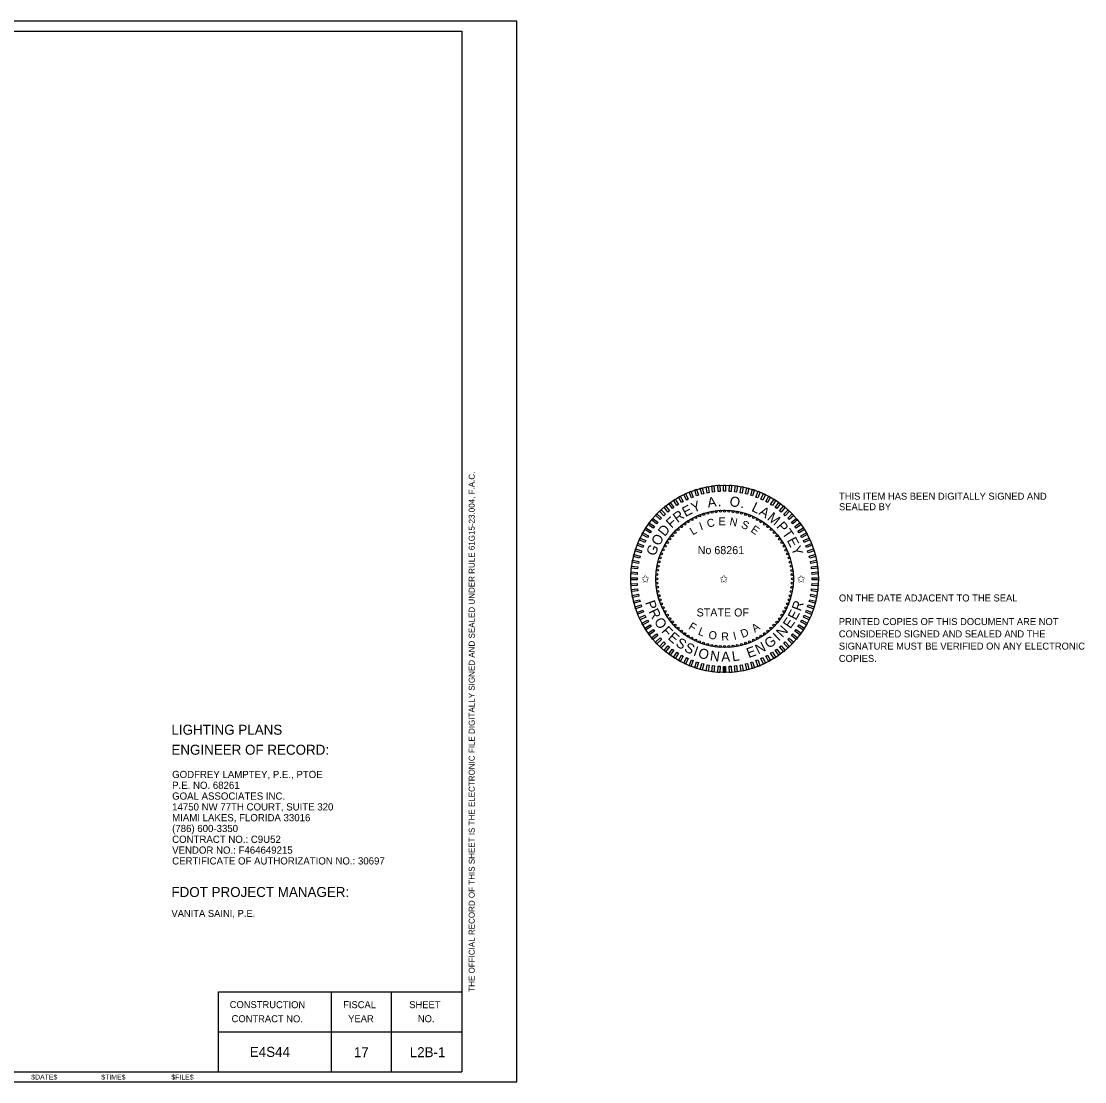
# Model space of a CAD drawing. Extents: x -820.2 to -798.1, y -2199.1 to -2188.5.
# Drawn here: x -808.68 to -798.05, y -2199.12 to -2188.52 of the extents above; entities that cross this region are included whole.
import ezdxf

# ---------------------------------------------------------------- set-up
doc = ezdxf.new("R2010")
doc.units = 0
for name, color, linetype in [('ActivePointCell_dp', 7, 'Continuous'), ('Logo_dp', 7, 'Continuous'), ('NonPlottingEle_dp', 7, 'Continuous'), ('PlotBorder_dp', 7, 'Continuous'), ('SheetBorder_dp', 7, 'Continuous'), ('SheetLines_dp', 7, 'Continuous'), ('TextLabel', 7, 'Continuous'), ('TextMinor', 7, 'Continuous'), ('TextMisc', 7, 'Continuous'), ('TextNotes', 7, 'Continuous'), ('TextShtNo', 7, 'Continuous')]:
    doc.layers.add(name, color=color, linetype=linetype)

msp = doc.modelspace()

# ---------------------------------------------------------------- linework, layer by layer
at = {"layer": 'ActivePointCell_dp'}
msp.add_line((-804.277, -2188.624), (-804.277, -2188.624), dxfattribs=at)
at = {"layer": 'Logo_dp'}
for p, q in [((-801.66, -2195.034), (-801.66, -2194.972)), ((-801.65, -2195.034), (-801.65, -2194.972)), ((-801.64, -2195.034), (-801.64, -2194.972))]:
    msp.add_line(p, q, dxfattribs=at)
for points in [[(-801.804, -2193.235), (-801.824, -2193.239), (-801.836, -2193.178), (-801.816, -2193.174)], [(-801.75, -2193.228), (-801.77, -2193.23), (-801.777, -2193.168), (-801.757, -2193.166)], [(-801.695, -2193.223), (-801.715, -2193.224), (-801.719, -2193.162), (-801.699, -2193.161)], [(-801.64, -2193.222), (-801.66, -2193.222), (-801.66, -2193.159), (-801.64, -2193.159)], [(-801.585, -2193.224), (-801.605, -2193.223), (-801.601, -2193.161), (-801.581, -2193.162)], [(-801.53, -2193.23), (-801.55, -2193.228), (-801.542, -2193.166), (-801.522, -2193.168)], [(-801.476, -2193.239), (-801.496, -2193.236), (-801.484, -2193.174), (-801.464, -2193.178)], [(-802.063, -2193.325), (-802.08, -2193.335), (-802.11, -2193.28), (-802.093, -2193.271)], [(-802.013, -2193.301), (-802.032, -2193.309), (-802.058, -2193.253), (-802.04, -2193.244)], [(-801.963, -2193.28), (-801.981, -2193.287), (-802.004, -2193.229), (-801.986, -2193.222)], [(-801.911, -2193.262), (-801.93, -2193.268), (-801.949, -2193.208), (-801.93, -2193.202)], [(-801.858, -2193.247), (-801.877, -2193.252), (-801.893, -2193.191), (-801.873, -2193.186)], [(-801.423, -2193.252), (-801.442, -2193.247), (-801.427, -2193.186), (-801.407, -2193.191)], [(-801.37, -2193.268), (-801.389, -2193.262), (-801.37, -2193.202), (-801.351, -2193.208)], [(-801.318, -2193.287), (-801.337, -2193.28), (-801.314, -2193.222), (-801.295, -2193.229)], [(-801.268, -2193.31), (-801.287, -2193.301), (-801.26, -2193.244), (-801.242, -2193.253)], [(-801.22, -2193.335), (-801.237, -2193.325), (-801.207, -2193.271), (-801.19, -2193.28)], [(-802.2, -2193.416), (-802.216, -2193.429), (-802.255, -2193.381), (-802.24, -2193.368)], [(-802.156, -2193.383), (-802.172, -2193.395), (-802.209, -2193.344), (-802.193, -2193.333)], [(-802.11, -2193.353), (-802.127, -2193.363), (-802.161, -2193.311), (-802.144, -2193.3)], [(-801.173, -2193.364), (-801.19, -2193.353), (-801.156, -2193.3), (-801.139, -2193.311)], [(-801.127, -2193.395), (-801.144, -2193.383), (-801.107, -2193.333), (-801.091, -2193.344)], [(-801.084, -2193.429), (-801.1, -2193.416), (-801.06, -2193.368), (-801.045, -2193.381)], [(-802.318, -2193.531), (-802.331, -2193.547), (-802.379, -2193.507), (-802.366, -2193.492)], [(-802.281, -2193.491), (-802.295, -2193.505), (-802.34, -2193.462), (-802.326, -2193.448)], [(-802.242, -2193.452), (-802.256, -2193.466), (-802.299, -2193.42), (-802.284, -2193.407)], [(-801.044, -2193.466), (-801.058, -2193.452), (-801.016, -2193.407), (-801.001, -2193.421)], [(-801.005, -2193.505), (-801.019, -2193.491), (-800.974, -2193.448), (-800.96, -2193.463)], [(-800.969, -2193.547), (-800.982, -2193.531), (-800.934, -2193.492), (-800.921, -2193.507)], [(-802.383, -2193.619), (-802.394, -2193.637), (-802.447, -2193.603), (-802.436, -2193.586)], [(-802.352, -2193.574), (-802.364, -2193.591), (-802.414, -2193.554), (-802.403, -2193.538)], [(-800.936, -2193.591), (-800.948, -2193.575), (-800.898, -2193.538), (-800.886, -2193.554)], [(-800.906, -2193.637), (-800.917, -2193.62), (-800.864, -2193.586), (-800.853, -2193.603)], [(-802.437, -2193.715), (-802.446, -2193.733), (-802.503, -2193.707), (-802.494, -2193.689)], [(-802.412, -2193.666), (-802.422, -2193.684), (-802.476, -2193.654), (-802.467, -2193.636)], [(-800.878, -2193.684), (-800.888, -2193.667), (-800.833, -2193.637), (-800.824, -2193.654)], [(-800.854, -2193.734), (-800.863, -2193.715), (-800.806, -2193.689), (-800.797, -2193.707)], [(-802.479, -2193.817), (-802.485, -2193.836), (-802.545, -2193.817), (-802.539, -2193.798)], [(-802.46, -2193.765), (-802.467, -2193.784), (-802.525, -2193.761), (-802.518, -2193.742)], [(-800.833, -2193.784), (-800.84, -2193.766), (-800.782, -2193.743), (-800.775, -2193.761)], [(-800.815, -2193.836), (-800.821, -2193.817), (-800.762, -2193.798), (-800.755, -2193.817)], [(-802.508, -2193.923), (-802.511, -2193.943), (-802.573, -2193.931), (-802.569, -2193.911)], [(-802.495, -2193.869), (-802.5, -2193.889), (-802.561, -2193.873), (-802.556, -2193.854)], [(-800.8, -2193.889), (-800.805, -2193.87), (-800.745, -2193.854), (-800.74, -2193.874)], [(-800.789, -2193.943), (-800.792, -2193.923), (-800.731, -2193.911), (-800.727, -2193.931)], [(-802.523, -2194.032), (-802.524, -2194.052), (-802.586, -2194.048), (-802.585, -2194.028)], [(-802.517, -2193.977), (-802.519, -2193.997), (-802.581, -2193.989), (-802.579, -2193.969)], [(-800.781, -2193.997), (-800.783, -2193.977), (-800.721, -2193.97), (-800.719, -2193.99)], [(-800.776, -2194.052), (-800.777, -2194.032), (-800.715, -2194.028), (-800.714, -2194.048)], [(-802.525, -2194.087), (-802.525, -2194.107), (-802.588, -2194.107), (-802.588, -2194.087)], [(-800.775, -2194.107), (-800.775, -2194.087), (-800.713, -2194.087), (-800.713, -2194.107)], [(-802.524, -2194.142), (-802.523, -2194.162), (-802.585, -2194.166), (-802.586, -2194.146)], [(-802.519, -2194.196), (-802.517, -2194.217), (-802.579, -2194.224), (-802.581, -2194.204)], [(-800.783, -2194.217), (-800.781, -2194.197), (-800.719, -2194.205), (-800.721, -2194.225)], [(-800.777, -2194.162), (-800.776, -2194.142), (-800.714, -2194.146), (-800.715, -2194.166)], [(-802.512, -2194.251), (-802.508, -2194.271), (-802.569, -2194.282), (-802.573, -2194.263)], [(-802.5, -2194.305), (-802.495, -2194.324), (-802.556, -2194.34), (-802.561, -2194.32)], [(-800.805, -2194.324), (-800.8, -2194.305), (-800.74, -2194.32), (-800.745, -2194.34)], [(-800.792, -2194.271), (-800.789, -2194.251), (-800.727, -2194.263), (-800.731, -2194.283)], [(-802.485, -2194.358), (-802.479, -2194.377), (-802.539, -2194.396), (-802.545, -2194.377)], [(-802.467, -2194.41), (-802.46, -2194.428), (-802.518, -2194.451), (-802.525, -2194.433)], [(-800.84, -2194.429), (-800.833, -2194.41), (-800.775, -2194.433), (-800.782, -2194.452)], [(-800.821, -2194.377), (-800.815, -2194.358), (-800.755, -2194.377), (-800.762, -2194.396)], [(-802.446, -2194.46), (-802.438, -2194.479), (-802.494, -2194.505), (-802.503, -2194.487)], [(-802.422, -2194.51), (-802.412, -2194.527), (-802.467, -2194.557), (-802.476, -2194.54)], [(-802.394, -2194.557), (-802.384, -2194.574), (-802.436, -2194.608), (-802.447, -2194.591)], [(-800.917, -2194.574), (-800.906, -2194.557), (-800.853, -2194.591), (-800.864, -2194.608)], [(-800.888, -2194.527), (-800.878, -2194.51), (-800.824, -2194.54), (-800.833, -2194.557)], [(-800.863, -2194.479), (-800.854, -2194.46), (-800.798, -2194.487), (-800.806, -2194.505)], [(-802.364, -2194.603), (-802.352, -2194.619), (-802.403, -2194.656), (-802.414, -2194.64)], [(-802.331, -2194.647), (-802.318, -2194.662), (-802.366, -2194.702), (-802.379, -2194.687)], [(-800.982, -2194.663), (-800.969, -2194.647), (-800.921, -2194.687), (-800.934, -2194.702)], [(-800.948, -2194.619), (-800.936, -2194.603), (-800.886, -2194.64), (-800.898, -2194.656)], [(-802.295, -2194.688), (-802.281, -2194.703), (-802.327, -2194.746), (-802.34, -2194.731)], [(-802.256, -2194.728), (-802.242, -2194.742), (-802.285, -2194.787), (-802.299, -2194.773)], [(-802.216, -2194.765), (-802.2, -2194.778), (-802.24, -2194.826), (-802.255, -2194.813)], [(-801.1, -2194.778), (-801.085, -2194.765), (-801.045, -2194.813), (-801.06, -2194.826)], [(-801.058, -2194.742), (-801.044, -2194.728), (-801.001, -2194.773), (-801.016, -2194.787)], [(-801.019, -2194.703), (-801.005, -2194.689), (-800.96, -2194.731), (-800.974, -2194.746)], [(-802.173, -2194.799), (-802.156, -2194.811), (-802.193, -2194.861), (-802.209, -2194.849)], [(-802.128, -2194.83), (-802.11, -2194.841), (-802.144, -2194.894), (-802.161, -2194.883)], [(-802.081, -2194.859), (-802.063, -2194.869), (-802.093, -2194.923), (-802.111, -2194.914)], [(-801.237, -2194.869), (-801.22, -2194.859), (-801.19, -2194.914), (-801.207, -2194.923)], [(-801.19, -2194.841), (-801.173, -2194.83), (-801.139, -2194.883), (-801.156, -2194.894)], [(-801.144, -2194.811), (-801.128, -2194.799), (-801.091, -2194.849), (-801.107, -2194.861)], [(-802.032, -2194.884), (-802.014, -2194.893), (-802.04, -2194.949), (-802.058, -2194.941)], [(-801.982, -2194.907), (-801.963, -2194.914), (-801.986, -2194.972), (-802.005, -2194.965)], [(-801.93, -2194.926), (-801.911, -2194.932), (-801.93, -2194.992), (-801.949, -2194.985)], [(-801.878, -2194.942), (-801.858, -2194.947), (-801.874, -2195.007), (-801.893, -2195.002)], [(-801.824, -2194.955), (-801.804, -2194.958), (-801.816, -2195.02), (-801.836, -2195.016)], [(-801.77, -2194.964), (-801.75, -2194.966), (-801.758, -2195.028), (-801.778, -2195.026)], [(-801.715, -2194.97), (-801.695, -2194.971), (-801.699, -2195.033), (-801.719, -2195.032)], [(-801.66, -2194.972), (-801.64, -2194.972), (-801.64, -2195.034), (-801.66, -2195.034)], [(-801.605, -2194.971), (-801.585, -2194.97), (-801.581, -2195.032), (-801.601, -2195.033)], [(-801.551, -2194.966), (-801.53, -2194.964), (-801.523, -2195.026), (-801.543, -2195.028)], [(-801.496, -2194.958), (-801.476, -2194.955), (-801.465, -2195.016), (-801.484, -2195.02)], [(-801.442, -2194.947), (-801.423, -2194.942), (-801.407, -2195.002), (-801.427, -2195.007)], [(-801.389, -2194.932), (-801.37, -2194.926), (-801.351, -2194.985), (-801.37, -2194.992)], [(-801.337, -2194.914), (-801.319, -2194.907), (-801.296, -2194.965), (-801.314, -2194.972)], [(-801.287, -2194.893), (-801.268, -2194.884), (-801.242, -2194.941), (-801.26, -2194.95)]]:
    msp.add_lwpolyline(points, close=True, dxfattribs=at)
for centre in [(-801.976, -2193.503), (-801.938, -2193.484), (-801.899, -2193.467), (-801.859, -2193.452), (-801.818, -2193.441), (-801.776, -2193.431), (-801.734, -2193.425), (-801.692, -2193.421), (-801.65, -2193.419), (-801.607, -2193.421), (-801.565, -2193.425), (-801.523, -2193.432), (-801.481, -2193.441), (-801.44, -2193.453), (-801.4, -2193.467), (-801.361, -2193.484), (-801.323, -2193.504), (-802.113, -2193.603), (-802.081, -2193.575), (-802.048, -2193.549), (-802.013, -2193.525), (-801.287, -2193.525), (-801.251, -2193.549), (-801.218, -2193.575), (-801.186, -2193.603), (-802.198, -2193.698), (-802.172, -2193.665), (-802.144, -2193.633), (-801.156, -2193.634), (-801.128, -2193.666), (-801.102, -2193.699), (-802.263, -2193.808), (-802.243, -2193.77), (-802.222, -2193.733), (-801.078, -2193.734), (-801.056, -2193.771), (-801.037, -2193.809), (-802.306, -2193.928), (-802.294, -2193.887), (-802.28, -2193.847), (-801.02, -2193.848), (-801.006, -2193.888), (-800.994, -2193.929), (-802.322, -2194.011), (-802.315, -2193.969), (-800.984, -2193.971), (-800.978, -2194.013), (-802.328, -2194.096), (-802.326, -2194.054), (-802.326, -2194.139), (-800.974, -2194.055), (-800.974, -2194.14), (-800.973, -2194.097), (-802.322, -2194.181), (-802.316, -2194.223), (-800.985, -2194.224), (-800.978, -2194.182), (-802.306, -2194.265), (-802.295, -2194.306), (-802.28, -2194.346), (-801.02, -2194.347), (-801.006, -2194.307), (-800.994, -2194.266), (-802.263, -2194.385), (-802.244, -2194.423), (-802.222, -2194.459), (-801.078, -2194.46), (-801.057, -2194.424), (-801.037, -2194.386), (-802.198, -2194.495), (-802.172, -2194.528), (-802.144, -2194.56), (-801.157, -2194.561), (-801.128, -2194.529), (-801.102, -2194.496), (-802.114, -2194.59), (-802.082, -2194.619), (-802.049, -2194.645), (-802.014, -2194.669), (-801.288, -2194.669), (-801.252, -2194.645), (-801.219, -2194.619), (-801.187, -2194.591), (-801.977, -2194.69), (-801.939, -2194.71), (-801.9, -2194.727), (-801.86, -2194.741), (-801.819, -2194.753), (-801.778, -2194.762), (-801.736, -2194.769), (-801.693, -2194.773), (-801.65, -2194.774), (-801.608, -2194.773), (-801.566, -2194.769), (-801.524, -2194.762), (-801.482, -2194.753), (-801.441, -2194.741), (-801.401, -2194.727), (-801.362, -2194.71), (-801.324, -2194.691)]:
    msp.add_circle(centre, 0.01, dxfattribs=at)
at = {"layer": 'NonPlottingEle_dp'}
for radius in [0.937, 0.687]:
    msp.add_circle((-801.65, -2194.097), radius, dxfattribs=at)
at = {"layer": 'PlotBorder_dp'}
msp.add_lwpolyline([(-820.227, -2199.124), (-803.727, -2199.124), (-803.727, -2188.524), (-820.227, -2188.524)], close=True, dxfattribs=at)
at = {"layer": 'SheetBorder_dp'}
for p, q in [((-819.677, -2188.624), (-804.277, -2188.624)), ((-804.277, -2188.624), (-804.277, -2199.024)), ((-819.677, -2199.024), (-804.277, -2199.024))]:
    msp.add_line(p, q, dxfattribs=at)
at = {"layer": 'SheetLines_dp'}
for p, q in [((-806.708, -2198.224), (-804.277, -2198.224)), ((-806.708, -2199.024), (-806.708, -2198.224)), ((-805.577, -2199.024), (-805.577, -2198.224)), ((-804.977, -2199.024), (-804.977, -2198.224)), ((-806.708, -2198.624), (-804.277, -2198.624))]:
    msp.add_line(p, q, dxfattribs=at)

# ---------------------------------------------------------------- texts
at = {"layer": 'Logo_dp'}
for s, height, rotation, p in [('A', 0.1, 8.8088, (-801.815, -2193.386)), ('O', 0.1, 352.1877, (-801.605, -2193.369)), ('E', 0.1, 28.1055, (-802.041, -2193.481)), ('Y', 0.1, 21.0633, (-801.962, -2193.438)), ('.', 0.1, 1.0418, (-801.717, -2193.371)), ('.', 0.1, 343.5268, (-801.496, -2193.384)), ('L', 0.1, 334.6727, (-801.388, -2193.416)), ('A', 0.1, 328.4096, (-801.315, -2193.449)), ('F', 0.1, 42.3772, (-802.18, -2193.596)), ('R', 0.1, 35.9269, (-802.121, -2193.54)), ('C', 0.08, 12.2025, (-801.818, -2193.585)), ('E', 0.08, 0.4186, (-801.71, -2193.562)), ('N', 0.08, 349.2914, (-801.605, -2193.56)), ('M', 0.1, 320.6426, (-801.231, -2193.5)), ('D', 0.1, 50.8569, (-802.248, -2193.68)), ('L', 0.08, 30.4021, (-801.969, -2193.663)), ('I', 0.08, 20.0117, (-801.886, -2193.613)), ('S', 0.08, 337.0221, (-801.492, -2193.582)), ('E', 0.08, 325.8663, (-801.396, -2193.622)), ('P', 0.1, 311.1966, (-801.138, -2193.577)), ('T', 0.1, 304.4563, (-801.081, -2193.641)), ('O', 0.1, 59.5178, (-802.304, -2193.775)), ('E', 0.1, 297.6315, (-801.031, -2193.712)), ('G', 0.1, 68.0518, (-802.345, -2193.875)), ('Y', 0.1, 290.5893, (-800.988, -2193.79)), ('P', 0.1, 289.4055, (-802.445, -2194.332)), ('R', 0.1, 69.5134, (-800.89, -2194.427)), ('R', 0.1, 296.1458, (-802.412, -2194.423)), ('E', 0.1, 62.4712, (-800.936, -2194.517)), ('O', 0.1, 303.9671, (-802.36, -2194.524)), ('F', 0.08, 328.7241, (-802.018, -2194.594)), ('A', 0.08, 34.4992, (-801.348, -2194.636)), ('N', 0.1, 47.1788, (-801.072, -2194.691)), ('E', 0.1, 55.4289, (-800.993, -2194.602)), ('F', 0.1, 312.628, (-802.288, -2194.626)), ('E', 0.1, 319.0783, (-802.224, -2194.694)), ('L', 0.08, 339.2916, (-801.921, -2194.653)), ('O', 0.08, 349.6821, (-801.816, -2194.692)), ('R', 0.08, 2.3398, (-801.682, -2194.714)), ('I', 0.08, 14.2037, (-801.554, -2194.708)), ('D', 0.08, 22.0128, (-801.472, -2194.689)), ('I', 0.1, 43.6456, (-801.11, -2194.725)), ('S', 0.1, 326.1206, (-802.147, -2194.76)), ('S', 0.1, 333.193, (-802.061, -2194.816)), ('I', 0.1, 340.2654, (-801.97, -2194.861)), ('E', 0.1, 19.8191, (-801.41, -2194.89)), ('N', 0.1, 26.8614, (-801.314, -2194.854)), ('G', 0.1, 35.1115, (-801.209, -2194.798)), ('O', 0.1, 343.7986, (-801.922, -2194.88)), ('N', 0.1, 352.4595, (-801.801, -2194.912)), ('A', 0.1, 0.7097, (-801.683, -2194.925)), ('L', 0.1, 8.4767, (-801.57, -2194.922))]:
    msp.add_text(s, height=height, rotation=rotation, dxfattribs=at).set_placement(p)
for s, p in [('No 68261', (-801.919, -2193.85)), ('✩', (-802.485, -2194.135)), ('✩', (-801.7, -2194.135)), ('✩', (-800.928, -2194.135)), ('STATE OF', (-801.93, -2194.473))]:
    msp.add_text(s, height=0.08, dxfattribs=at).set_placement(p)
at = {"layer": 'TextLabel'}
for s, height, p in [('LIGHTING PLANS', 0.1, (-807.177, -2195.655)), ('ENGINEER OF RECORD:', 0.1, (-807.177, -2195.855)), ('GODFREY LAMPTEY, P.E., PTOE', 0.07202, (-807.17, -2196.088)), ('P.E. NO. 68261', 0.07202, (-807.17, -2196.196)), ('GOAL ASSOCIATES INC. ', 0.07202, (-807.17, -2196.304)), ('14750 NW 77TH COURT, SUITE 320', 0.07202, (-807.17, -2196.412)), ('MIAMI LAKES, FLORIDA 33016', 0.07202, (-807.17, -2196.52)), ('(786) 600-3350', 0.07202, (-807.17, -2196.628)), ('CONTRACT NO.: C9U52', 0.07202, (-807.17, -2196.736)), ('VENDOR NO.: F464649215', 0.07202, (-807.17, -2196.844)), ('CERTIFICATE OF AUTHORIZATION NO.: 30697', 0.07202, (-807.17, -2196.952)), ('E4S44', 0.1, (-806.394, -2198.875))]:
    msp.add_text(s, height=height, dxfattribs=at).set_placement(p)
at = {"layer": 'TextMinor'}
for s, p in [('$DATE$', (-808.578, -2199.102)), ('$TIME$', (-807.878, -2199.102)), ('$FILE$', (-807.178, -2199.102))]:
    msp.add_text(s, height=0.05, rotation=360, dxfattribs=at).set_placement(p)
at = {"layer": 'TextMisc'}
msp.add_text('THE OFFICIAL RECORD OF THIS SHEET IS THE ELECTRONIC FILE DIGITALLY SIGNED AND SEALED UNDER RULE 61G15-23.004, F.A.C.', height=0.06, rotation=90, dxfattribs=at).set_placement((-804.147, -2198.224))
for s, p in [('THIS ITEM HAS BEEN DIGITALLY SIGNED AND ', (-800.507, -2193.306)), ('SEALED BY', (-800.507, -2193.411)), ('ON THE DATE ADJACENT TO THE SEAL', (-800.508, -2194.323)), ('PRINTED COPIES OF THIS DOCUMENT ARE NOT ', (-800.509, -2194.559)), ('CONSIDERED SIGNED AND SEALED AND THE ', (-800.509, -2194.682)), ('SIGNATURE MUST BE VERIFIED ON ANY ELECTRONIC ', (-800.509, -2194.804)), ('COPIES.', (-800.509, -2194.927))]:
    msp.add_text(s, height=0.07, dxfattribs=at).set_placement(p)
at = {"layer": 'TextNotes'}
for s, height, p in [('FDOT PROJECT MANAGER:', 0.1, (-807.177, -2197.277)), ('VANITA SAINI, P.E.', 0.07, (-807.177, -2197.476))]:
    msp.add_text(s, height=height, dxfattribs=at).set_placement(p)
for s, p in [('CONSTRUCTION', (-806.595, -2198.387)), ('FISCAL', (-805.461, -2198.388)), ('SHEET', (-804.801, -2198.388)), ('CONTRACT NO.', (-806.576, -2198.528)), ('YEAR', (-805.411, -2198.528)), ('NO.', (-804.715, -2198.528))]:
    msp.add_text(s, height=0.07, rotation=359.8607, dxfattribs=at).set_placement(p)
at = {"layer": 'TextShtNo'}
for s, p in [('17', (-805.354, -2198.878)), ('L2B-1', (-804.796, -2198.878))]:
    msp.add_text(s, height=0.1, dxfattribs=at).set_placement(p)

doc.saveas('drawing.dxf')
